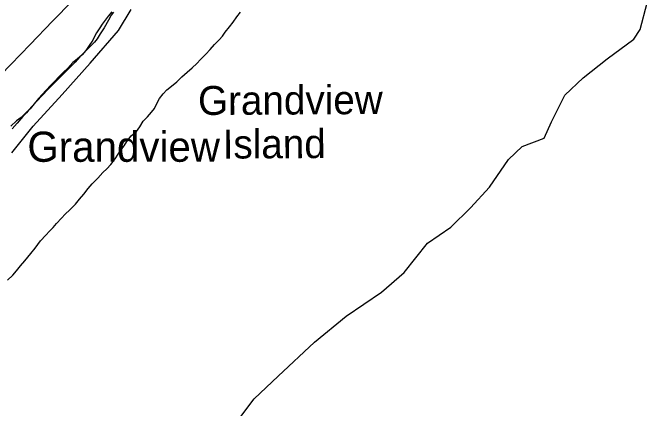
# Model space of a CAD drawing. Extents: x 6.3 to 40.3, y 9 to 31.
# Drawn here: x 10.708 to 12.373, y 23.853 to 24.889 of the extents above; entities that cross this region are included whole.
import ezdxf

# ---------------------------------------------------------------- set-up
doc = ezdxf.new("R2010")
doc.units = 0
for name, color, linetype in [('Default', 7, 'Continuous'), ('GM_X_Major_River', 7, 'Continuous'), ('GM_X_Major_River_Text', 7, 'Continuous'), ('GM_X_Section', 7, 'Continuous'), ('GM_X_State_Route', 7, 'Continuous'), ('GM_X_Unincorporated_Text', 7, 'Continuous'), ('SH_Cut_Line', 7, 'Continuous')]:
    doc.layers.add(name, color=color, linetype=linetype)

msp = doc.modelspace()

# ---------------------------------------------------------------- linework, layer by layer
at = {"layer": 'Default'}
for points in [[(11.3069, 23.8314), (11.3415, 23.8775), (11.4048, 23.9373), (11.4999, 24.0257), (11.5828, 24.0941), (11.6753, 24.157), (11.7345, 24.2088), (11.7957, 24.2849), (11.8577, 24.3272), (11.9093, 24.3781), (11.959, 24.432), (12.0085, 24.5041), (12.0444, 24.5385), (12.1018, 24.5602), (12.1213, 24.603), (12.1559, 24.673), (12.2042, 24.7182), (12.2669, 24.7681), (12.3375, 24.8197), (12.3542, 24.8446), (12.3726, 24.9147)], [(10.7062, 24.5216), (10.7617, 24.5919), (10.8376, 24.6747), (10.9112, 24.7567), (10.9858, 24.8421), (11.0192, 24.8969)]]:
    msp.add_lwpolyline(points, dxfattribs=at)
at = {"layer": 'GM_X_Major_River'}
for points in [[(10.9682, 24.8913), (10.9589, 24.8798), (10.9433, 24.859), (10.9371, 24.849), (10.9282, 24.836), (10.9231, 24.8264), (10.9183, 24.8168), (10.9072, 24.8007), (10.9002, 24.7896), (10.8902, 24.7788), (10.8775, 24.7671), (10.8659, 24.7586), (10.8532, 24.7432), (10.8405, 24.7327), (10.8282, 24.7204)], [(10.9066, 24.4286), (10.9166, 24.4406), (10.9315, 24.4553), (10.9449, 24.4703), (10.955, 24.4803), (10.9654, 24.4915), (10.9772, 24.5062), (10.9846, 24.5188), (10.992, 24.5288), (11.0002, 24.5399), (11.0075, 24.5515), (11.019, 24.5661), (11.0329, 24.5777), (11.0414, 24.5896), (11.0502, 24.6046), (11.0614, 24.6162), (11.0725, 24.6281), (11.0803, 24.6377), (11.0869, 24.6527), (11.0931, 24.6641), (11.1032, 24.6761), (11.1128, 24.6865), (11.1248, 24.6966), (11.1386, 24.7078), (11.1517, 24.7206), (11.1662, 24.7334), (11.1789, 24.7446), (11.1916, 24.7562), (11.2009, 24.7662), (11.2147, 24.7801), (11.2262, 24.7921), (11.2378, 24.806), (11.2501, 24.8176), (11.2582, 24.8276), (11.2656, 24.8376), (11.2768, 24.8522), (11.2864, 24.8645), (11.2964, 24.8783), (11.306, 24.8907)], [(10.8282, 24.7204), (10.819, 24.7099), (10.8074, 24.6984), (10.7962, 24.686), (10.7854, 24.6748), (10.7762, 24.6644), (10.765, 24.6498), (10.7543, 24.6367), (10.7416, 24.6255), (10.7308, 24.6146), (10.7184, 24.6053), (10.7031, 24.5914)], [(10.6951, 24.1881), (10.7085, 24.2016), (10.7181, 24.2132), (10.7285, 24.2259), (10.7401, 24.2386), (10.7479, 24.2482), (10.7556, 24.2582), (10.7668, 24.2721), (10.7738, 24.2817), (10.7816, 24.2913), (10.795, 24.306), (10.8047, 24.3168), (10.8143, 24.3264), (10.8229, 24.3368), (10.8359, 24.3507), (10.8456, 24.3611), (10.8579, 24.3724), (10.8732, 24.3878), (10.8839, 24.4005), (10.8947, 24.4136), (10.9066, 24.4286)]]:
    msp.add_lwpolyline(points, dxfattribs=at)
at = {"layer": 'GM_X_Section'}
msp.add_lwpolyline([(10.9723, 24.8903), (10.9667, 24.8822), (10.9597, 24.8696), (10.9479, 24.849), (10.938, 24.8333), (10.9298, 24.8206), (10.9228, 24.8118), (10.9168, 24.8056), (10.884, 24.7729), (10.8721, 24.7594), (10.8553, 24.7429), (10.8355, 24.7229), (10.8094, 24.6967), (10.8008, 24.6874), (10.7874, 24.674), (10.771, 24.6559), (10.7583, 24.6436), (10.7505, 24.6343), (10.7442, 24.627), (10.7349, 24.617), (10.73, 24.6109), (10.72, 24.5997), (10.7069, 24.5848)], dxfattribs=at)
at = {"layer": 'GM_X_State_Route'}
msp.add_lwpolyline([(10.5848, 24.6304), (10.604, 24.6503), (10.6208, 24.6678), (10.6271, 24.6744), (10.6527, 24.7008), (10.6799, 24.729), (10.7007, 24.7504), (10.7038, 24.7535), (10.7543, 24.8058), (10.8131, 24.8664), (10.8327, 24.8872), (10.8454, 24.9), (10.8683, 24.9237), (10.8938, 24.95), (10.9069, 24.9641), (10.9227, 24.9816), (10.9375, 24.9992), (10.9472, 25.0107)], dxfattribs=at)
at = {"layer": 'SH_Cut_Line'}
msp.add_lwpolyline([(10.7062, 24.5216), (10.7617, 24.5919), (10.8376, 24.6747), (10.9112, 24.7567), (10.9858, 24.8421), (11.0192, 24.8969)], dxfattribs=at)

# ---------------------------------------------------------------- texts
at = {"layer": 'GM_X_Major_River_Text'}
for s, rotation, p in [('Grandview', 0.3053, (11.1945, 24.6209)), ('Island', 0.3058, (11.2592, 24.5068))]:
    msp.add_text(s, height=0.07576, rotation=rotation, dxfattribs=at).set_placement(p)
at = {"layer": 'GM_X_Unincorporated_Text'}
msp.add_text('Grandview', height=0.07898, rotation=0, dxfattribs=at).set_placement((10.7469, 24.4984))

doc.saveas('drawing.dxf')
